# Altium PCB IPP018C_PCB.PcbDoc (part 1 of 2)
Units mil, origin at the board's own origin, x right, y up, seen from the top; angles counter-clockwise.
Board outline 3500 x 2700 mil, 4 copper layers (Top Layer, Mid-Layer 1, Mid-Layer 2, Bottom Layer), stack 90 mil thick; 62 components, 59 nets, 295 pads, 117 vias.
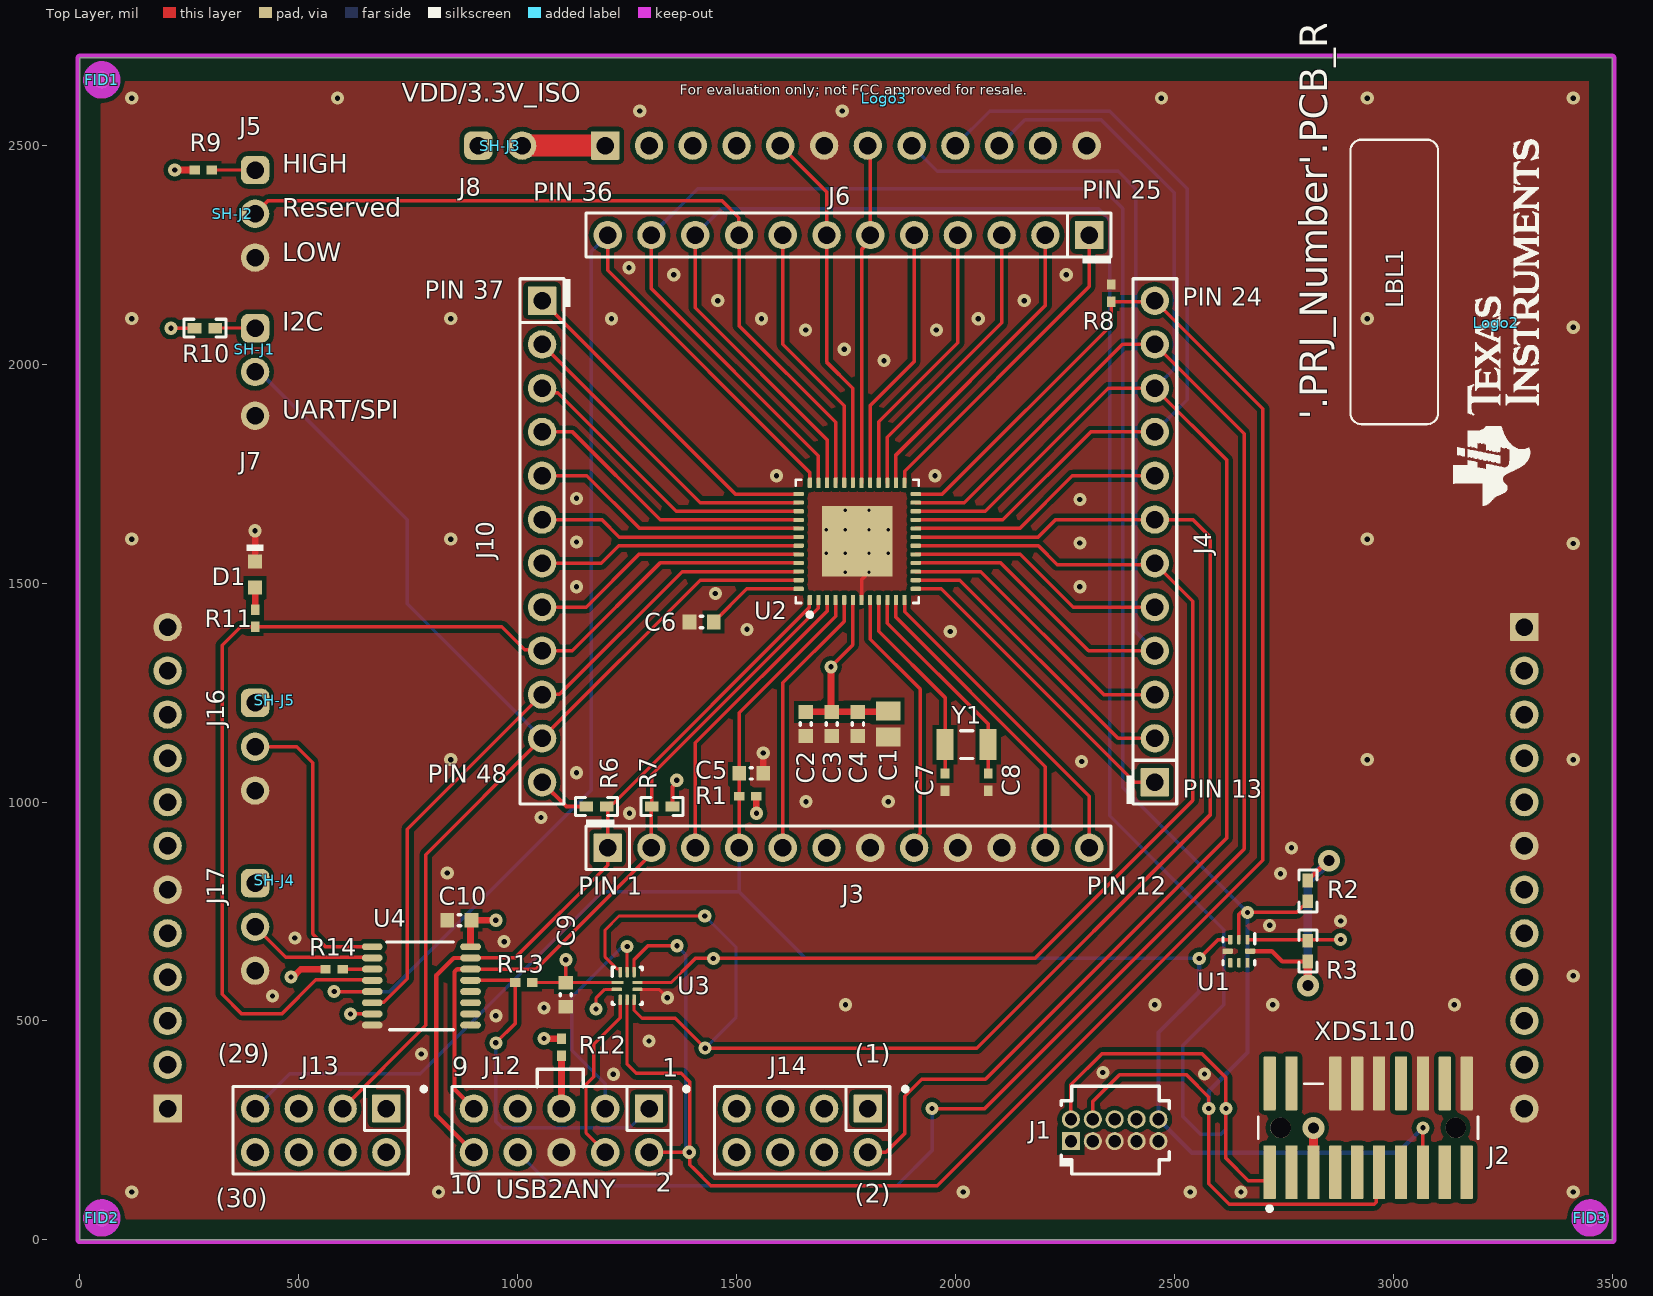
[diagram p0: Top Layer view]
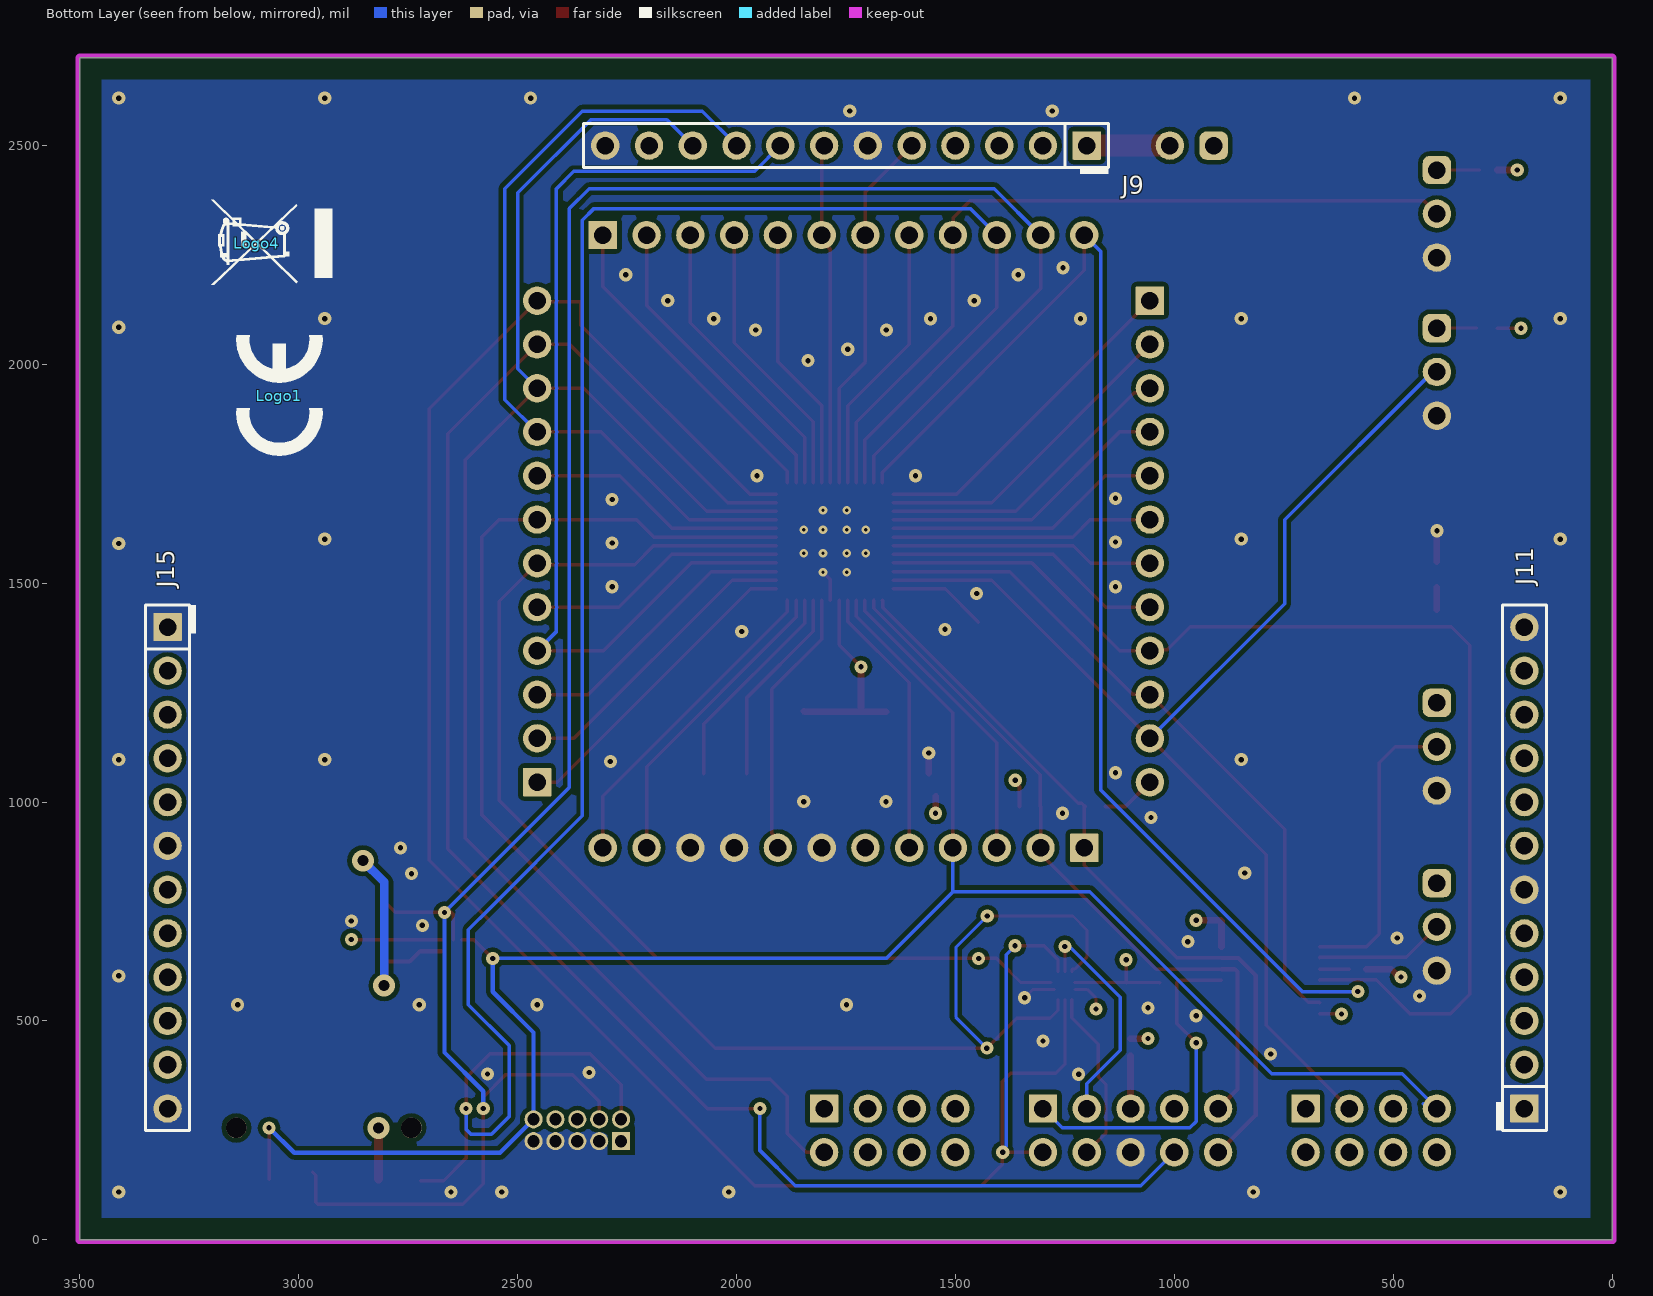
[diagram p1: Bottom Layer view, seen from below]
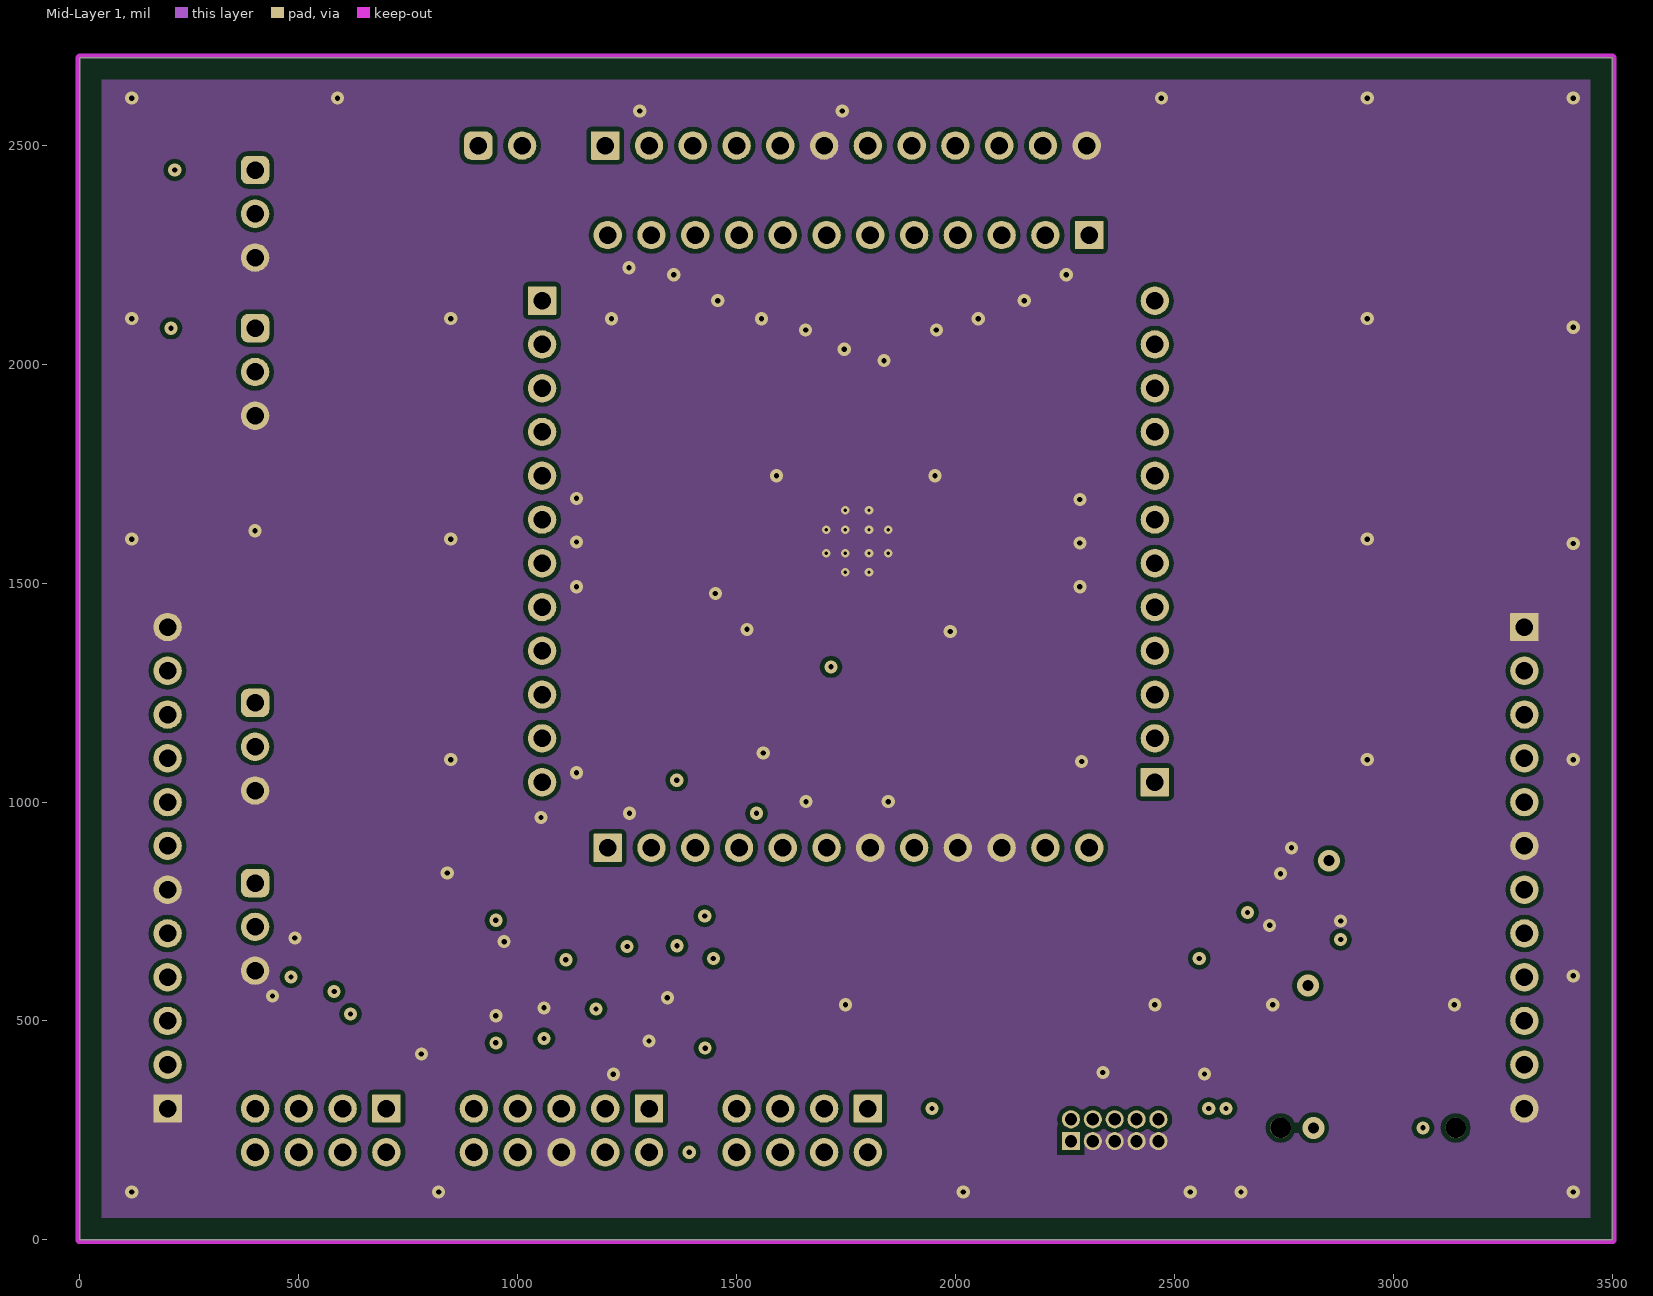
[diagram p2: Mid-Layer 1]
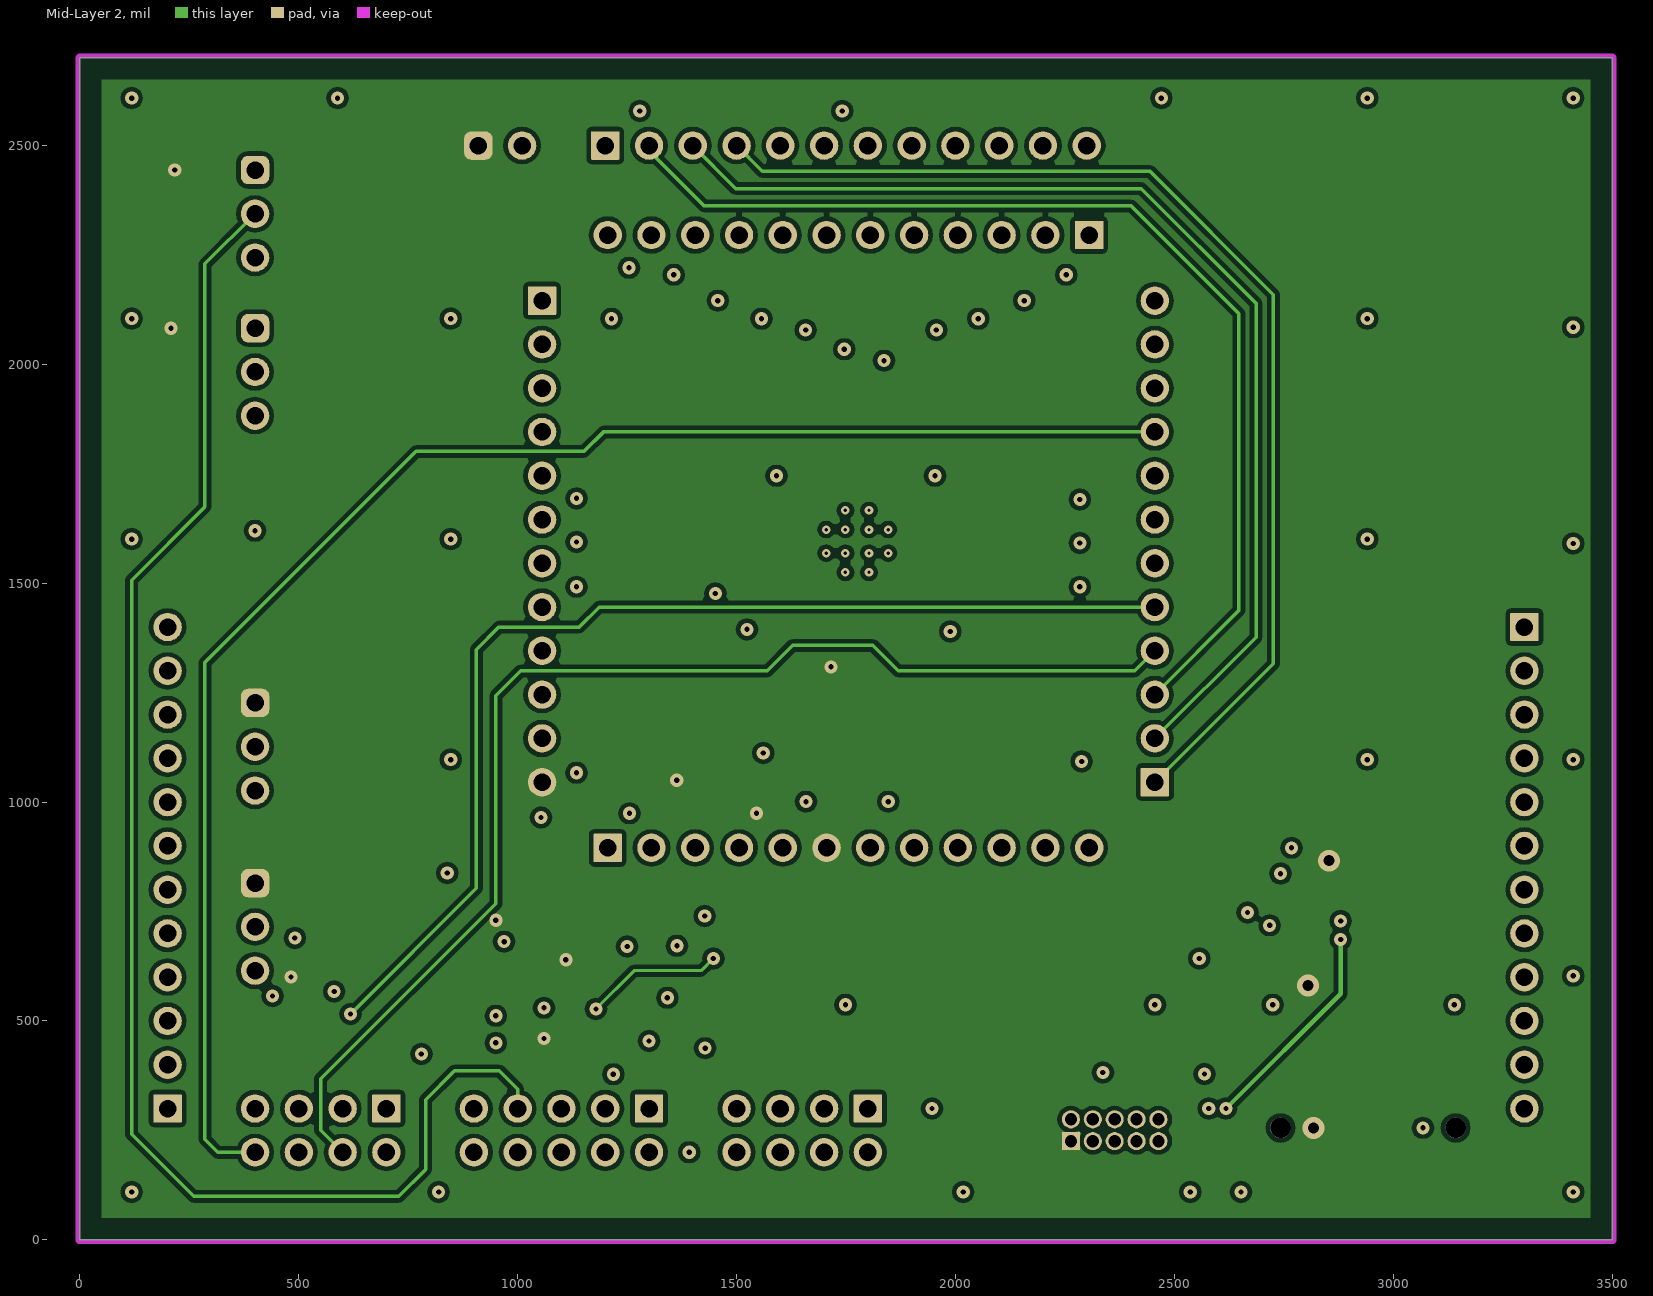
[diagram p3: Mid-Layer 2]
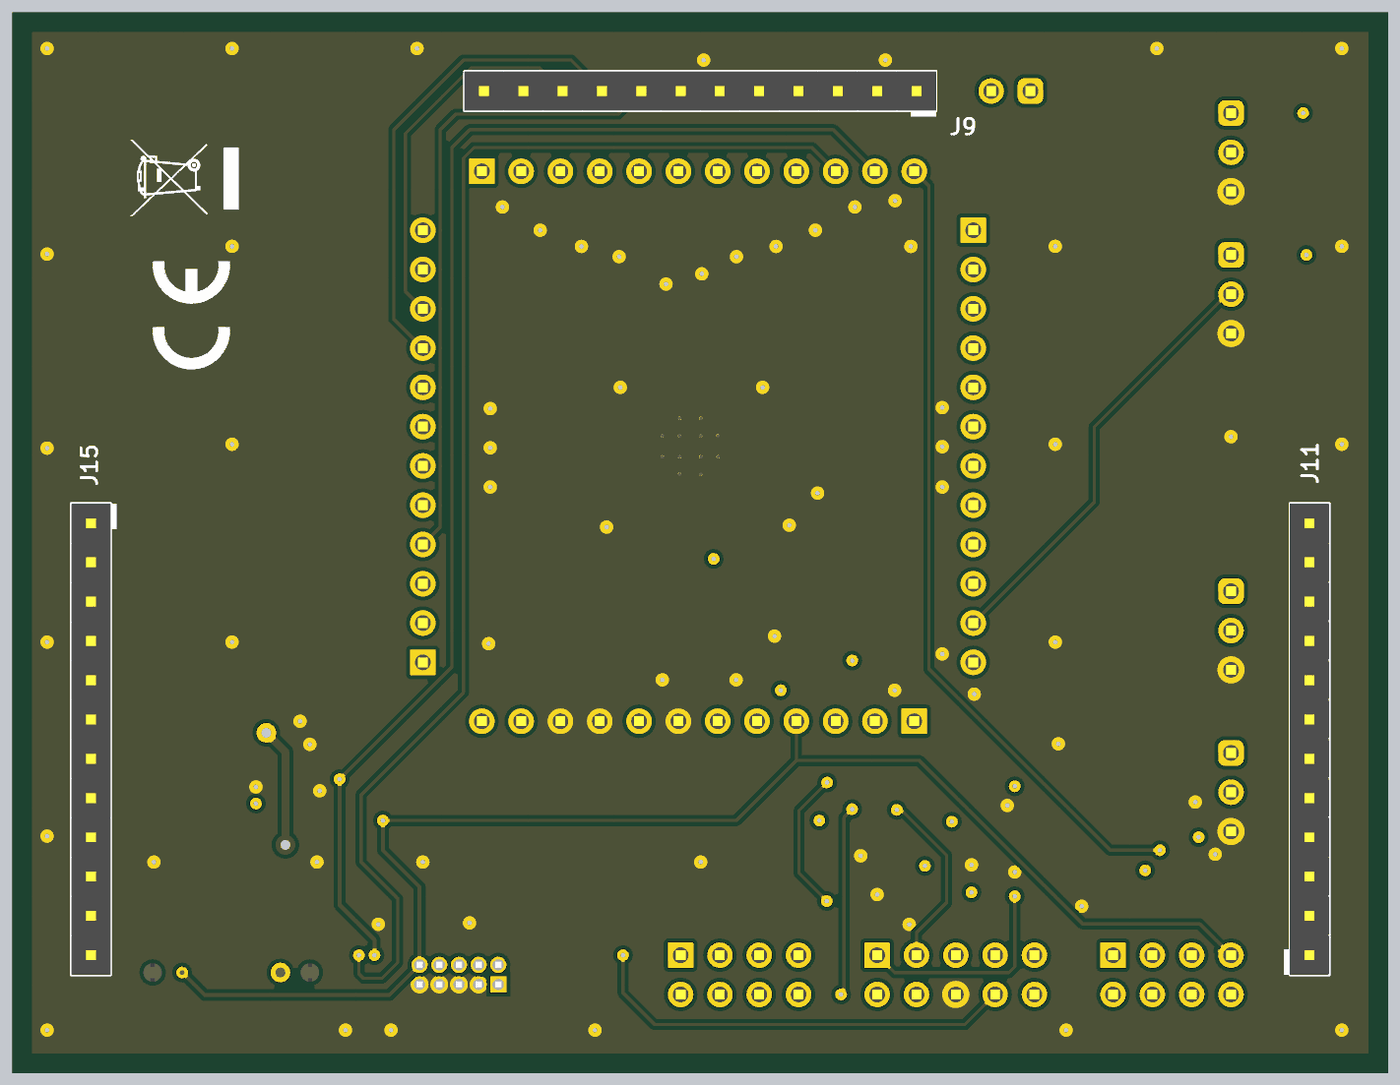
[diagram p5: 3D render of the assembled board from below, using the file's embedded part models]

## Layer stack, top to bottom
Top Solder: solder mask 0.4, Solder Resist, Dk 3.5
Top Layer: signal copper 1.4
Dielectric1: core 59.2, FR-4 High Tg, Dk 4.8
Mid-Layer 1: signal copper 1.4
Dielectric3: dielectric 12.6, FR-4, Dk 4.8
Mid-Layer 2: signal copper 1.4
Dielectric2: dielectric 12.6, FR-4, Dk 4.8
Bottom Layer: signal copper 1.4
Bottom Solder: solder mask 0.4, Solder Resist, Dk 3.5

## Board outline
0,0 3500,0 3500,2700 0,2700

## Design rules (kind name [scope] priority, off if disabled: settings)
AcuteAngle [All] p1: minimum=4.50000000000000E+0001 checktracksonly=FALSE
AssemblyTestPointUsage [All] p1: valid=2
BoardOutlineClearance BoardOutlineClearance_MountingHoles [OnCopper and InComponentClass('Mounting Holes')] p1: gap=39.37 ignorepadtopadclearanceinfootprint=FALSE
BoardOutlineClearance BoardOutlineClearance_Poly [OnCopper and IsPoly] p2: gap=25 ignorepadtopadclearanceinfootprint=FALSE
BoardOutlineClearance [OnCopper and Not InComponentClass('Logo') and not InComponentClass('FiducialMark') and not InRegion(1000,500,4000,800) and not InPoly] p3: gap=40 ignorepadtopadclearanceinfootprint=FALSE
Clearance Clearance_Keepouts [((IsTrack Or IsArc) And Not InPoly) And IsFree and IsKeepOut vs ((IsTrack Or IsArc) And Not InPoly) And IsFree and IsKeepOut] p1: gap=0 ignorepadtopadclearanceinfootprint=FALSE
Clearance Clearance_Poly [InPolygon] p2: gap=10 ignorepadtopadclearanceinfootprint=TRUE
Clearance Clearance_FiducialMark [IsKeepOut and InComponentClass('FiducialMark') vs IsPad and InComponentClass('FiducialMark')] p3: gap=0 ignorepadtopadclearanceinfootprint=FALSE
Clearance [All] p4: gap=7.87 ignorepadtopadclearanceinfootprint=TRUE
ComponentClearance ComponentClearance_MountingHoles_FiducialMarks [InComponentClass('Mounting Holes') vs InComponentClass('FiducialMark')] p1: gap=50 collisioncheckmode=3 verticalgap=10 showdistances=FALSE
ComponentClearance ComponentClearance_Shunt [InComponentClass('Header') vs InComponentClass('Shunt')] p2: gap=0 collisioncheckmode=3 verticalgap=0 showdistances=FALSE
ComponentClearance ComponentClearance_Logo [InComponentClass('Logo')] p3: gap=30 collisioncheckmode=3 verticalgap=10 showdistances=FALSE
ComponentClearance ComponentClearance_ScrewToNut [(HasFootprint('NY PMS 440 0025 PH')) vs (HasFootprint('Keystone_1902C'))] p4: gap=5 collisioncheckmode=3 verticalgap=10 showdistances=FALSE
ComponentClearance ComponentClearance_MountingHoles [InComponentClass('Mounting Holes')] p5: gap=100 collisioncheckmode=3 verticalgap=100000 showdistances=FALSE
ComponentClearance ComponentClearance_SmallPassives [HasFootprint('0201*') or HasFootprint('0402*') or HasFootprint('0508') or HasFootprint('0603*') or HasFootprint('0612') or HasFootprint('0805*') or HasFootprint('0815*') or HasFootprint('0830*') or HasFootprint('1206*') or HasFootprint('1210*') or HasFootprint('1808*') or HasFootprint('1812*') or HasFootprint('1825*') or HasFootprint('2010*') or HasFootprint('2220*') or HasFootprint('2225*') or HasFootprint('2512*') or HasFootprint('2728*') or HasFootprint('3518*') vs HasFootprint('0201*') or HasFootprint('0402*') or HasFootprint('0508') or HasFootprint('0603*') or HasFootprint('0612') or HasFootprint('0805*') or HasFootprint('0815*') or HasFootprint('0830*') or HasFootprint('1206*') or HasFootprint('1210*') or HasFootprint('1808*') or HasFootprint('1812*') or HasFootprint('1825*') or HasFootprint('2010*') or HasFootprint('2220*') or HasFootprint('2225*') or HasFootprint('2512*') or HasFootprint('2728*') or HasFootprint('3518*')] p6: gap=14.96 collisioncheckmode=3 verticalgap=10 showdistances=FALSE
ComponentClearance ComponentClearance_THtoSMT [IsThruComponent vs IsSMTComponent] p7: gap=30 collisioncheckmode=3 verticalgap=30 showdistances=FALSE
ComponentClearance ComponentClearance_THtoTH [IsThruComponent vs IsThruComponent] p8: gap=20 collisioncheckmode=3 verticalgap=30 showdistances=FALSE
ComponentClearance [All] p9: gap=20 collisioncheckmode=3 verticalgap=10 showdistances=FALSE
DiffPairsRouting [All] p1: maxlimit=100 minlimit=10 mostfreqgap=10 toplayer_minwidth=15 toplayer_maxwidth=15 toplayer_prefwidth=15 midlayer1_minwidth=15 midlayer1_maxwidth=15 midlayer1_prefwidth=15 midlayer2_minwidth=15 midlayer2_maxwidth=15 midlayer2_prefwidth=15 bottomlayer_minwidth=15 bottomlayer_maxwidth=15 bottomlayer_prefwidth=15 maxuncoupledlength=1000
FabricationTestPointUsage TestPointUsage [All] p1: valid=2 allowmultiple=FALSE
FabricationTestpoint Testpoint [All] p1: side=3 testpointundercomponent=TRUE minsize=40 maxsize=100 preferedsize=60 minholesize=0 maxholesize=40 preferedholesize=32 testpointgrid=1 allowsidetop=TRUE allowsidebottom=TRUE usegrid=TRUE gridtolerance=0.01
FanoutControl Fanout_LCC [IsLCC] p1: bgadir=Out bgaviamode=Centered fanoutstyle=Auto fanoutdirection=Alternating viagrid=1 // Fanout_LCC (Default Rule)
FanoutControl Fanout_BGA [IsBGA] p2: bgadir=Out bgaviamode=Centered fanoutstyle=Auto fanoutdirection=Alternating viagrid=1 // Fanout_BGA (Default Rule)
FanoutControl Fanout_Default [All] p4: bgadir=Out bgaviamode=Centered fanoutstyle=Auto fanoutdirection=Alternating viagrid=1 // Fanout_Default (Default Rule)
FanoutControl Fanout_Small [(CompPinCount < 5)] p5: bgadir=Out bgaviamode=Centered fanoutstyle=Auto fanoutdirection=OutThenIn viagrid=1 // Fanout_Small (Default Rule)
HoleSize [All] p1: absolutevalues=TRUE maxlimit=251 minlimit=7.87 maxpercent=80.000 minpercent=20.000
MinimumAnnularRing MinimumAnnularRing_ThermalPadVias [IsVia and InAnyComponent] p1: minimumring=5.91
MinimumAnnularRing [All] p2: minimumring=7.87
MinimumSolderMaskSliver MinimumSolderMaskSliver_Logo [InComponentClass('Logo') vs InComponentClass('Logo')] p1: minsoldermaskwidth=0.7
MinimumSolderMaskSliver [All] p2: minsoldermaskwidth=3.94
PlaneConnect [All] p1: planeconnectstyle=Direct reliefexpansion=10 reliefentries=4 reliefconductorwidth=10 reliefairgap=10
PolygonConnect [All] p1: connectstyle=Direct reliefconductorwidth=10 reliefentries=4 polygonreliefangle="90 Angle" airgapwidth=10
RoutingLayers [All] p1: top layer_v5=TRUE mid layer 1_v5=FALSE mid layer 2_v5=TRUE bottom layer_v5=TRUE
RoutingVias ThermalPadVias [IsVia and InAnyComponent] p1: holewidth=7.87 width=19.68 viastyle="Through Hole" minholewidth=7.87 minwidth=19.68 maxholewidth=12.99 maxwidth=23.62
RoutingVias [All] p2: holewidth=16 width=34 viastyle="Through Hole" minholewidth=7.87 minwidth=24 maxholewidth=40 maxwidth=65
SilkToBoardRegionClearance [Not ((IsComment or IsDesignator) And (Hide <> 'False')) and not InRegion(1000,500,4000,800)] p1:
SilkToSilkClearance SilkToSilkClearance_Pb-FreeLogo [(HasFootprint('Pb-Free_Overlay_Medium') OR HasFootprint('Pb-Free_Overlay_Small')) vs (HasFootprint('Pb-Free_Overlay_Medium') OR HasFootprint('Pb-Free_Overlay_Small'))] p1: silktosilkclearance=0
SilkToSilkClearance [All] p2: silktosilkclearance=3.94
SilkToSolderMaskClearance SilkToComponentPadClearance [(IsPad or IsFill or IsRegion) and InAnycomponent] p1: minsilkscreentomaskgap=5 clearancetoexposedcopper=TRUE
SilkToSolderMaskClearance "Silk to Solder Mask Opening" [All] p2: minsilkscreentomaskgap=3.94 clearancetoexposedcopper=FALSE
SolderMaskExpansion [All] p1: expansion=1.97 istentingtop=FALSE
SupplyNets "Schematic Supply Nets_1" [InNet('VDD')] p1: voltage=0.000
SupplyNets "Schematic Supply Nets" [InNet('GND_ISO')] p2: voltage=0.000
UnRoutedNet [All] p1: checkbadconnections=TRUE
Width [All] p1: maxlimit=50 minlimit=6 preferedwidth=10 midlayer1_maxwidth=20 midlayer2_maxwidth=20 minimp=50.000000 maximp=50.000000 favimp=50.000000 checkconnectedcopper=TRUE
13 further rules are at their usual default settings.

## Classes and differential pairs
component class Shunt: SH-J1 SH-J2 SH-J3 SH-J4 SH-J5
component class IPP018C: 7 C1 C2 C3 C4 C5 C6 C7 C8 C9 C10 D1 J1 J2 J3 J4 J5 J6 J7 J8 J9 J10 J11 J12 J13 J14 J15 J16 J17 R1 R2 R3 R6 R7 R8 R9 R10 R11 R12 R13 R14 SH-J1 SH-J2 SH-J3 SH-J4 SH-J5 U1 U2 U3 U4 Y1
component class Header: 7 J3 J4 J5 J6 J7 J8 J9 J10 J11 J12 J13 J14 J15 J16 J17
component class Logo: Logo2
component class IPP018C_Hardware: FID1 FID2 FID3 LBL1 Logo1 Logo2 Logo3 Logo4 ZZ1 ZZ2 ZZ3 ZZ4
component class FiducialMark: FID1 FID2 FID3
component class AssemblyNote: ZZ1 ZZ2 ZZ3 ZZ4
component class Label: LBL1

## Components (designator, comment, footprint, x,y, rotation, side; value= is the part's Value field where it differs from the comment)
C1 "885012207026" 0805L 1846.46,1178.53 r90 top value=10uF
C2 "885012206046" 0603L 1657.87,1178.53 r90 top value=0.1uF
C3 "885012206046" 0603L 1717.52,1178.53 r90 top value=0.1uF
C4 "885012206046" 0603L 1777.17,1178.53 r90 top value=0.1uF
C5 "885012206083" 0603L 1533.46,1065.59 r0 top value=1000pF
C6 "GCM188R71C474KA55D" 0603L 1420.16,1411.42 r0 top value=0.47uF
C7 "CL05C120JB5NNNC" 0402L 1976.18,1045.59 r270 top value=12pF
C8 "CL05C120JB5NNNC" 0402L 2074.8,1045.59 r270 top value=12pF
C9 "885012206046" 0603L 1110,560 r90 top value=0.1uF
C10 "885012206046" 0603L 866.61,730 r0 top value=0.1uF
D1 "LTST-C190KGKT" LED_LTST-C190_G 400,1520 r90 top value=Green
FID1 "Fiducial" Fiducial10-20 50,2650 r0 top
FID2 "Fiducial" Fiducial10-20 50,50 r0 top
FID3 "Fiducial" Fiducial10-20 3450,50 r0 top
J1 "FTSH-105-01-F-D-K" Samtec_FTSH-105-01-x-D-K 2363.8,250.42 r90 top
J2 "FTR-110-03-G-D-LC-06" FP-FTR-110-03-G-D-LC-06_HDR19-MFG 2942.91,255.91 r0 top
J3 "TSW-112-07-G-S" TSW-112-07-G-S 1755.59,895.59 r0 top locked
J4 "TSW-112-07-G-S" TSW-112-07-G-S 2455.59,1595.59 r90 top
J5 "TSW-103-07-G-S" TSW-103-07-G-S 400,2344.09 r270 top
J6 "TSW-112-07-G-S" TSW-112-07-G-S 1755.59,2295.59 r180 top
J7 "TSW-103-07-G-S" TSW-103-07-G-S 400,1982.7 r270 top
J8 "TSW-102-07-G-S" TSW-102-07-G-S 960,2500 r0 top
J9 "TSW-112-07-G-S" TSW-112-07-G-S 1750,2500 r0 bottom
J10 "TSW-112-07-G-S" TSW-112-07-G-S 1055.59,1595.59 r270 top
J11 "TSW-112-07-G-S" TSW-112-07-G-S 200,850 r90 bottom
J12 "TSW-105-07-G-D" TSW-105-07-G-D 1100,250 r180 top
J13 "TSW-104-07-G-D" TSW-104-07-G-D 550,250 r180 top
J14 "TSW-104-07-G-D" TSW-104-07-G-D 1650,250 r180 top
J15 "TSW-112-07-G-S" TSW-112-07-G-S 3300,850 r270 bottom
J16 "TSW-103-07-G-S" TSW-103-07-G-S 400,1126.51 r270 top
J17 "TSW-103-07-G-S" TSW-103-07-G-S 400,715 r270 top
LBL1 "THT-14-423-10" Label_650x200 3002.52,2188.34 r90 top
Logo1 "CE Mark" CE_Mark_5mm 3044.36,1928.93 r90 bottom
Logo2 "Texas Instruments" TI_Stacked_Overlay_Small 3235,2095.52 r90 top
Logo3 "FCC disclaimer" FCC_disclaimer 1837.11,2608.27 r0 top
Logo4 "WEEE logo" WEEE_Minimum 3096.14,2277.16 r90 bottom
R1 "CRCW040247K0JNED" 0402L 1525.59,1013.78 r0 top value=47k
R2 "CRCW04024K70JNED" 0402 2805.12,797.24 r270 top value=4.7k
R3 "CRCW04024K70JNED" 0402 2805.12,659.45 r90 top value=4.7k
R6 "CRCW04024K70JNED" 0402 1180,989.84 r180 top value=4.7k
R7 "CRCW04024K70JNED" 0402 1330,989.84 r0 top value=4.7k
R8 "CRCW04022M00FKED" 0402L 2355.59,2162.97 r90 top value=2.00Meg
R9 "CRCW040247K0JNED" 0402L 281.5,2444.09 r180 top value=47k
R10 "CRCW04024K70JNED" 0402 285.43,2082.7 r0 top value=4.7k
R11 "CRCW0402330RJNED" 0402L 400,1420 r270 top value=330
R12 "ERJ-2GE0R00X" 0402L 1100,440 r270 top value=0
R13 "CRCW040247K0JNED" 0402L 1013.78,587.87 r0 top value=47k
R14 "CRCW040247K0JNED" 0402L 580.71,618.39 r180 top value=47k
SH-J1 "SPC02SYAN" SPC02SYAN 399.63,2034.5 r90 top value=1x2
SH-J2 "SPC02SYAN" SPC02SYAN 348.65,2344.09 r180 top value=1x2
SH-J3 "SPC02SYAN" SPC02SYAN 960,2500 r180 top value=1x2
SH-J4 "SPC02SYAN" SPC02SYAN 445.21,821.42 r180 top value=1x2
SH-J5 "SPC02SYAN" SPC02SYAN 445.21,1232.91 r0 top value=1x2
U1 "TPD6E004RSER" RSE0008A 2647.64,659.45 r270 top
U2 "MSPM0G1107SRGZ" RGZ0048B-MFG 1775.59,1595.59 r90 top
U3 "TS3A5223RSWR" RSW0010A 1250,580 r0 top
U4 "PCA9538PWR" PW0016A_L 780,580 r0 top
Y1 "FC-135 32.7680KA-AG0" Epson_FC-135 2025.39,1131.18 r0 top
ZZ1 "This Assembly Note is for PCB labels only" AssemblyNoteLabel 155.47,5079.73 r0 top
ZZ2 "These assemblies are ESD sensitive, ESD precautions shall be observed." AssemblyNote 155.47,4970.85 r0 top
ZZ3 "These assemblies must be clean and free from flux and all contaminants. Use of no clean flux is not acceptable." AssemblyNote 155.47,4882.29 r0 top
ZZ4 "These assemblies must comply with workmanship standards IPC-A-610 Class 2, unless otherwise specified." AssemblyNote 155.47,4793.73 r0 top

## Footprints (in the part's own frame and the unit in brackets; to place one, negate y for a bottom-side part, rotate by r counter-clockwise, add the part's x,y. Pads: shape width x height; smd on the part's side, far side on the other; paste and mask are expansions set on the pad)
0402 [mm] "0402 from SM-752 data"
  rect 0.8x0.6 smd: 1(-0.6,0) 2(0.6,0)
  silkscreen extent -1.22,-0.52 1.22,0.52, body extent -0.55,-0.3 0.55,0.3, height 0.6
0402L [mm] "0402 from SM-752 data"
  rect 0.6x0.5 smd: 1(-0.5,0) 2(0.5,0)
  body extent -0.55,-0.3 0.55,0.3, height 0.6
0603L [mm] "0603 from SM-752 data"
  rect 0.8x0.85 smd: 1(-0.7,0) 2(0.7,0)
  silkscreen extent -0.07,-0.33 0.07,0.33, body extent -0.87,-0.47 0.87,0.47, height 1
0805L [mm] "0805 from SM-752 data"
  rect 1.1x1.4 smd: 1(-0.75,0) 2(0.75,0)
  body extent -1.1,-0.72 1.1,0.72, height 1.45
AssemblyNote [mil] "Assembly Note"
AssemblyNoteLabel [mil] "Assembly Note for PCB Labels"
CE_Mark_5mm [mil] "Minimum text height for CE Mark"
  silkscreen extent -138,-98 138,98
Epson_FC-135 [mm] "SMD, 2-Leads, Body 3.2x1.5mm"
  rect 1x1.8 smd: 1(-1.25,0) 2(1.25,0)
  silkscreen extent -0.35,-0.8 0.35,0.8, body extent -1.65,-0.8 1.65,0.8, height 0.9
FCC_disclaimer [mil]
Fiducial10-20 [mm]
  round 1 smd mask+0.5: 1(0,0)
  Top Layer keep-out circle w1.178: c0,0 r0.5
FP-FTR-110-03-G-D-LC-06_HDR19-MFG [mm]
  rrect14% 0.711x3.125 smd paste+0 mask+0: 1(-5.715,-2.578) 2(-5.715,2.578) 3(-4.445,-2.578) 4(-4.445,2.578) 5(-3.175,-2.578) 7(-1.905,-2.578) 8(-1.905,2.578) 9(-0.635,-2.578) 10(-0.635,2.578) 11(0.635,-2.578) 12(0.635,2.578) 13(1.905,-2.578) 14(1.905,2.578) 15(3.175,-2.578) 16(3.175,2.578) 17(4.445,-2.578) 18(4.445,2.578) 19(5.715,-2.578) 20(5.715,2.578)
  round 1.194 hole 1.194 unplated paste-2539.97 mask+0: ""(-5.08,0) ""(5.08,0)
  silkscreen extent -6.38,-4.81 6.38,2.56, body extent -6.48,-4.24 6.48,4.24, height 0.25
Label_650x200 [mil] "Thermal Transfer Label"
  round 1 on Mech13: 0(0,0)
  silkscreen extent -325,-100 325,100, body extent -325,-100 325,100, height 1
LED_LTST-C190_G [mm] "Lite-On"
  rect 0.8x0.8 smd: 1(-0.75,0) 2(0.75,0)
  silkscreen extent 1.37,-0.5 1.75,0.5, body extent -0.85,-0.45 0.85,0.45, height 0.9
PW0016A_L [mm] "TSOP, 16-Leads, Body 5x4.4mm, Pitch 0.65mm, IPC High Density"
  oval 1.2x0.4 smd: 1(-2.85,2.275) 2(-2.85,1.625) 3(-2.85,0.975) 4(-2.85,0.325) 5(-2.85,-0.325) 6(-2.85,-0.975) 7(-2.85,-1.625) 8(-2.85,-2.275) 9(2.85,-2.275) 10(2.85,-1.625) 11(2.85,-0.975) 12(2.85,-0.325) 13(2.85,0.325) 14(2.85,0.975) 15(2.85,1.625) 16(2.85,2.275)
  silkscreen extent -2,-2.55 1.85,2.55, body extent -3.21,-2.5 3.21,2.5, height 1
RGZ0048B-MFG [mm]
  rrect42% 0.6x0.24 smd paste+0 mask+0: 1(-3.4,2.75) 2(-3.4,2.25) 3(-3.4,1.75) 4(-3.4,1.25) 5(-3.4,0.75) 6(-3.4,0.25) 7(-3.4,-0.25) 8(-3.4,-0.75) 9(-3.4,-1.25) 10(-3.4,-1.75) 11(-3.4,-2.25) 12(-3.4,-2.75) 25(3.4,-2.75) 26(3.4,-2.25) 27(3.4,-1.75) 28(3.4,-1.25) 29(3.4,-0.75) 30(3.4,-0.25) 31(3.4,0.25) 32(3.4,0.75) 33(3.4,1.25) 34(3.4,1.75) 35(3.4,2.25) 36(3.4,2.75)
  rrect42% 0.24x0.6 smd paste+0 mask+0: 13(-2.75,-3.4) 14(-2.25,-3.4) 15(-1.75,-3.4) 16(-1.25,-3.4) 17(-0.75,-3.4) 18(-0.25,-3.4) 19(0.25,-3.4) 20(0.75,-3.4) 21(1.25,-3.4) 22(1.75,-3.4) 23(2.25,-3.4) 24(2.75,-3.4) 37(2.75,3.4) 38(2.25,3.4) 39(1.75,3.4) 40(1.25,3.4) 41(0.75,3.4) 42(0.25,3.4) 43(-0.25,3.4) 44(-0.75,3.4) 45(-1.25,3.4) 46(-1.75,3.4) 47(-2.25,3.4) 48(-2.75,3.4)
  rrect2% 4.1x4.1 smd paste-1000 mask+0: 49(0,0)
  silkscreen extent -4.37,-3.57 3.57,3.57, body extent -3.8,-3.8 3.8,3.8, height 0.25
RSE0008A [mm] "QFN, 8-Leads, Body 1.5x1.5mm, Pitch 0.5mm, TI Recommended"
  rrect40% 0.55x0.25 smd: 1(-0.675,0.5) 3(-0.675,-0.5) 5(0.675,-0.5) 7(0.675,0.5)
  rrect50% 0.55x0.2 smd: 2(-0.675,0) 6(0.675,0)
  rrect33% 0.3x0.6 smd: 4(0,-0.65) 8(0,0.65)
  silkscreen extent -1.02,-0.92 0.77,0.93, body extent -0.75,-0.75 0.75,0.75, height 0.6
RSW0010A [mm] "QFN, 10-Leads, Body 1.8x1.4 mm, Pitch 0.4mm, TI Recommended"
  rrect50% 0.7x0.2 smd: 1(-0.55,0.2)
  rrect50% 0.6x0.2 smd: 2(-0.6,-0.2) 6(0.6,-0.2) 7(0.6,0.2)
  rrect50% 0.2x0.6 smd: 3(-0.4,-0.8) 4(0,-0.8) 5(0.4,-0.8) 8(0.4,0.8) 9(0,0.8) 10(-0.4,0.8)
  silkscreen extent -0.88,-1.08 0.88,1.08, body extent -0.7,-0.9 0.7,0.9, height 0.56
Samtec_FTSH-105-01-x-D-K [mm] "Header, 1.27 mm, 5x2, TH"
  rect 1.05x1.05 hole 0.71: 1(-0.635,2.54)
  round 1.05 hole 0.71: 2(0.635,2.54) 3(-0.635,1.27) 4(0.635,1.27) 5(-0.635,0) 6(0.635,0) 7(-0.635,-1.27) 8(0.635,-1.27) 9(-0.635,-2.54) 10(0.635,-2.54)
  silkscreen extent -2.54,-3.17 2.54,3.2, body extent -2.54,-3.17 2.54,3.1, height 5.73
SPC02SYAN [mil] "SULLINS"
  round 1 on Mech3: 0(0,0)
  body extent -98,-47 99,47, height 366
TI_Stacked_Overlay_Small [mil]
  silkscreen extent -418,-98 418,98
TSW-102-07-G-S [mm] "Samtec 100mil, 1x2, 230 mil above insulator"
  rrect50% 1.65x1.65 hole 1.016: 1(-1.27,0)
  round 1.65 hole 1.016: 2(1.27,0)
  body extent -2.54,-1.27 2.54,1.27, height 8.38
TSW-103-07-G-S [mm] "Samtec 100mil, 1x3, 230 mil above insulator"
  rrect50% 1.65x1.65 hole 1.016: 1(-2.54,0)
  round 1.65 hole 1.016: 2(0,0) 3(2.54,0)
  body extent -3.81,-1.27 3.81,1.27, height 8.38
TSW-104-07-G-D [mm] "Samtec 100mil, 2x4, 230 mil above insulator"
  rrect6% 1.65x1.65 hole 1.016: 1(-3.81,-1.27)
  round 1.65 hole 1.016: 2(-3.81,1.27) 3(-1.27,-1.27) 4(-1.27,1.27) 5(1.27,-1.27) 6(1.27,1.27) 7(3.81,-1.27) 8(3.81,1.27)
  silkscreen extent -6.11,-2.54 5.08,2.54, body extent -5.08,-2.54 5.08,2.54, height 8.38
TSW-105-07-G-D [mm] "Samtec 100mil, 2x5, 230 mil above insulator"
  rrect6% 1.65x1.65 hole 1.016: 1(-5.08,-1.27)
  round 1.65 hole 1.016: 2(-5.08,1.27) 3(-2.54,-1.27) 4(-2.54,1.27) 5(0,-1.27) 6(0,1.27) 7(2.54,-1.27) 8(2.54,1.27) 9(5.08,-1.27) 10(5.08,1.27)
  silkscreen extent -7.38,-2.54 6.35,2.54, body extent -6.35,-2.54 6.35,2.54, height 8.38
TSW-112-07-G-S [mm] "Samtec 100mil, 1x12, 230 mil above insulator"
  rrect6% 1.65x1.65 hole 1.016 mask+0: 1(-13.97,0)
  round 1.65 hole 1.016 mask+0: 2(-11.43,0) 3(-8.89,0) 4(-6.35,0) 5(-3.81,0) 6(-1.27,0) 7(1.27,0) 8(3.81,0) 9(6.35,0) 10(8.89,0) 11(11.43,0) 12(13.97,0)
  silkscreen extent -15.24,-1.27 15.24,1.65, body extent -15.24,-1.27 15.24,1.27, height 8.38
WEEE_Minimum [mil] "WEEElie bin"
  silkscreen extent -95,-172 99,104

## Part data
C1: library part CMP-0007691-2, "CAP, CERM, 10 uF, 10 V, +/- 10%, X7R, 0805", Cap_Case=0805, Manufacturer="Wurth Elektronik", Supplier Part Number 1=710-885012207026, TempCo=X7R, Tolerance_%=10%, Value1=Unknown, Value2=10V, ValueDisplayed=10uF
C2 C3 C4 C9 C10: library part CMP-0006829-4, "CAP, CERM, 0.1 uF, 16 V, +/- 10%, X7R, 0603", Cap_Case=0603, Manufacturer="Wurth Elektronik", Supplier Part Number 1=710-885012206046, TempCo=X7R, Tolerance_%=10%, Value1=Unknown, Value2=16V, ValueDisplayed=0.1uF
C5: library part CMP-0064933-4, "CAP, CERM, 1000 pF, 50 V,+/- 10%, X7R, 0603", Cap_Case=0603, Manufacturer="Wurth Elektronik", Supplier Part Number 1=732-8001-1-ND, TempCo=X7R, Tolerance_%=10%, Value1=Unknown, Value2=50V, ValueDisplayed=1000pF
C6: library part CMP-0007138-4, "CAP, CERM, 0.47 uF, 16 V, +/- 10%, X7R, AEC-Q200 Grade 1, 0603", Cap_Case=0603, Manufacturer=MuRata, Supplier Part Number 1=490-4775-1-ND, TempCo=X7R, Tolerance_%=10%, Value1=Unknown, Value2=16V, ValueDisplayed=0.47uF
C7 C8: library part CMP-0006345-2, "CAP, CERM, 12 pF, 50 V, +/- 5%, C0G/NP0, 0402", Cap_Case=0402, Manufacturer="Samsung Electro-Mechanics", Supplier Part Number 1=1276-1178-1-ND, TempCo=C0G/NP0, Tolerance_%=5%, Value1=Unknown, Value2=50V, ValueDisplayed=12pF
D1: library part CMP-0002840-2, "LED, Green, SMD", Color=green, Manufacturer=Lite-On, Value1=W, Value2=2V
FID1 FID2 FID3: library part CMP-0077181-1, "Fiducial mark.  There is nothing to buy or mount.", Manufacturer=N/A
J1: library part CMP-0075533-2, "Header, 1.27 mm, 5x2, Gold, TH", Color=Black, Manufacturer=Samtec, Supplier Part Number 1=FTSH-105-01-F-D-K-ND
J2: library part CMP-0092655-1, Current_A=3.1A, Digikey Part Number=SAM8791-ND, Manufacturer=Samtec, Mouser Part Number=200-FTR11003GDLC06, Operating Temperature Range="-55°C to +125°C"
J3 J4 J6 J9 J10 J11 J15: library part CMP-0075424-1, "Header, 100mil, 12x1, Gold, TH", Color=Black, Current_A=6.3A, Manufacturer=Samtec, Supplier Part Number 1=SAM1029-12-ND, Voltage_V=550V
J5 J7 J16 J17: library part CMP-0075407-2, "Header, 100mil, 3x1, Gold, TH", Color=Black, Current_A=6.3A, Manufacturer=Samtec, Supplier Part Number 1=SAM1029-03-ND, Voltage_V=550V
J8: library part CMP-0075405-2, "Header, 100mil, 2x1, Gold, TH", Color=Black, Current_A=6.3A, Manufacturer=Samtec, Supplier Part Number 1=SAM1029-02-ND, Voltage_V=550V
J12: library part CMP-0075410-2, "Header, 100mil, 5x2, Gold, TH", Color=Black, Current_A=6.3A, Manufacturer=Samtec, Supplier Part Number 1=SAM1028-05-ND, Voltage_V=550V
J13 J14: library part CMP-0075408-2, "Header, 100mil, 4x2, Gold, TH", Color=Black, Current_A=6.3A, Manufacturer=Samtec, Supplier Part Number 1=SAM1028-04-ND, Voltage_V=550V
LBL1: library part CMP-0003625-1, "Thermal Transfer Printable Labels, 0.650\" W x 0.200\" H - 10,000 per roll", Manufacturer=Brady, Supplier Part Number 1=97C5133
Logo1: library part CMP-0074844-1
Logo2: library part CMP-0074838-1, "Texas Instrument Corporate Signature"
Logo3: library part CMP-0074847-1, "FCC_disclaimer"
Logo4: library part CMP-0074769-1
R1 R9 R13 R14: library part CMP-0026935-3, "RES, 47 k, 5%, 0.063 W, AEC-Q200 Grade 0, 0402", Manufacturer=Vishay-Dale, Power_W=63mW, Supplier Part Number 1=541-47KJCT-ND, TempCo="200 ppm/C", Tolerance_%=5%, Value2=0.063W, Value_Code=47k0, ValueDisplayed=47k
R2 R3 R6 R7 R10: library part CMP-0026938-5, "RES, 4.7 k, 5%, 0.063 W, AEC-Q200 Grade 0, 0402", Manufacturer=Vishay-Dale, Power_W=63mW, Supplier Part Number 1=541-4.7KJCT-ND, TempCo="200 ppm/C", Tolerance_%=5%, Value2=0.063W, Value_Code=4k70, ValueDisplayed=4.7k
R8: library part CMP-0026245-2, "RES, 2.00 M, 1%, 0.063 W, AEC-Q200 Grade 0, 0402", Manufacturer=Vishay-Dale, Power_W=63mW, Supplier Part Number 1=541-2.00MLCT-ND, TempCo="100 ppm/C", Tolerance_%=1%, Value2=0.063W, Value_Code=2M00, ValueDisplayed=2.00M
R11: library part CMP-0026906-3, "RES, 330, 5%, 0.063 W, AEC-Q200 Grade 0, 0402", Manufacturer=Vishay-Dale, Power_W=63mW, Supplier Part Number 1=541-330JCT-ND, TempCo="200 ppm/C", Tolerance_%=5%, Value2=0.063W, Value_Code=330R, ValueDisplayed=330
R12: library part CMP-0026992-3, "RES, 0, 5%, 0.1 W, AEC-Q200 Grade 0, 0402", Manufacturer=Panasonic, Power_W=100mW, Supplier Part Number 1=P0.0JCT-ND, TempCo="600 ppm/C", Tolerance_%=5%, Value2=0.1W, Value_Code=0000, ValueDisplayed=0
SH-J1 SH-J2 SH-J3 SH-J4 SH-J5: library part CMP-0003642-1, "Shunt, 100mil, Flash Gold, Black", Manufacturer="Sullins Connector Solutions", Supplier Part Number 1=S9001-ND
U1: library part CMP-0043125-4, "Low-Capacitance 6-Channel +/-15 kV ESD Protection Array for High-Speed Data Interfaces, RSE0008A (UQFN-8)", Breakdown Voltage(Min)(V)=6, IO Capacitance(Typ)(pF)=1.6, IO Leakage Current(nA)=1, Manufacturer="Texas Instruments"
U2: library part CMP-0097891-1, "Mixed-Signal Microcontrollers", Frequency_Fixed=80MHz, Manufacturer="Texas Instruments", Max Supply Voltage=3.6V, Min Supply Voltage=1.62V, Operating Temperature Range="-40°C to +125°C"
U3: library part CMP-0085520-1, "0.5Ω Dual SPDT Bidirectional Analog Switch, RSW0010A (UQFN-10)", Alternate Manufacturer="Texas Instruments", Operating Temperature Range="-40 to 85 C", Rating=Catalog
U4: library part CMP-0043202-2, "Remote 8-Bit I2C and SMBus Low-Power I/O Expander With Interrupt Output, Reset, and Config Registers, PW0016A (TSSOP-16)", 5V Tolerant I/O=Yes, Manufacturer="Texas Instruments", Max Frequency(kHz)=400, Operating Temperature Range="-40 to 85 C", Rating=Catalog
Y1: library part CMP-0079303-1, "Crystal, 32.768 KHz, 20 ppm, 7 pF, SMD", Frequency_Fixed=32.768kHz, Frequency Stability="20 ppm", Load Capacitance="7 pF", Manufacturer=Epson, Supplier Part Number 1=732-FC135-32.76KAAG0
ZZ1: library part CMP-0003616-3
ZZ2: library part CMP-0077236-1
ZZ3: library part CMP-0077237-1
ZZ4: library part CMP-0077238-1

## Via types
v1: diameter 30, hole 12, Top Layer to Bottom Layer, 102 vias
v2: diameter 19.68, hole 7.87, Top Layer to Bottom Layer, tented both sides, 12 vias
v3: diameter 50, hole 25, Top Layer to Bottom Layer, 2 vias
v4: diameter 50, hole 25, Top Layer to Bottom Layer, tented both sides, 1 vias

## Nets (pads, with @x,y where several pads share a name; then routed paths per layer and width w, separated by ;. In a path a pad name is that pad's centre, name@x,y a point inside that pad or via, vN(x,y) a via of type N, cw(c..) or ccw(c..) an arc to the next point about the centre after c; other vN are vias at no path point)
3.3V_ISO: J8.2 J9.1 | length 190
  Top Layer w50: J8.2@1010,2500 J9.1@1200,2500
GND_ISO: C1.1 C2.1 C3.1 C4.1 C5.2 C6.1 C7.2 C8.2 C9.1 C10.1 D1.2 J1.3 J1.5 J1.7 J1.9 J2.8 J2.10 J2.12 J2.16 J2.20 J3.7 J3.9 J3.10 J5.3 J7.3 J9.6 J9.12 J11.1 J11.6 J11.12 J12.6 J15.1 J15.6 J15.12 J16.3 J17.3 R8.2 U1.4 U2.7 U2.49 U3.6 U4.8 | length 263.3
  Top Layer w7: U3.6@1273.62,572.13 1322.59,572.13 v1(1341.79,552.93)
  Top Layer w8: U2.7@1785.43,1461.73 1785.43,1507.6 v2(1802.56,1524.72)
  Top Layer w15: D1.2@400,1549.53 v1(400,1620) ; C5.2@1561.02,1065.59 v1(1561.02,1112.2)
  other v1: 118.11,109.25 819.37,109.25 2017.72,109.25 2536.57,109.25 2652.32,109.25 3411.32,109.25 1218.47,378.24 2568.9,378.58 2336.8,382.12 779.91,424.51 1300,454.42 950,511.81 1060,530 1748.8,537.11 2455.59,537.11 2724.8,537.11 3139.76,537.11 440.07,556.93 3411.32,603.15 969.01,681.18 490.83,689.82 2717.91,718.5 2880.12,728.35 2742.91,836.61 839.05,838.09 2767.91,895.59 1053.12,964.65 1255.59,974.41 1658.61,1001.02 1846.46,1001.02 1134.49,1067.01 2288.38,1093.05 846.9,1097.04 2940.86,1097.04 3411.32,1097.04 1988.19,1389.91 1523.62,1394.64 1451.52,1476.38 1134.49,1491.87 2284.17,1491.87 3411.32,1590.94 2284.17,1591.73 1134.49,1594.51 118.11,1600.79 846.9,1600.79 2940.86,1600.79 2284.17,1691.59 1134.49,1693.97 1591.32,1745.59 1953.34,1745.59 1837.07,2008.48 1746.06,2034.5 1657.87,2078.34 1956.34,2078.34 3411.32,2084.84 1214.26,2104.36 1557.15,2104.36 2052.26,2104.36 118.11,2104.53 846.9,2104.53 2940.86,2104.53 1457.15,2145.59 2157.15,2145.59 1356.61,2204.72 2253.11,2204.72 1254.41,2220.73 1278.95,2578.74 1741.39,2578.74 118.11,2608.27 588.57,2608.27 2470.4,2608.27 2940.86,2608.27 3411.32,2608.27
  other v2: 1748.62,1524.72 1704.72,1568.62 1748.62,1568.62 1802.56,1568.62 1846.46,1568.62 1704.72,1622.56 1748.62,1622.56 1802.56,1622.56 1846.46,1622.56 1748.62,1666.46 1802.56,1666.46
NetC6_2: C6.2 U2.48 | length 225.5
  Top Layer w8: C6.2@1447.72,1411.42 1523.62,1487.32 U2.48@1641.73,1487.32
NetC7_1: C7.1 U2.9 Y1.1 | length 459.2
  Top Layer w8: U2.9@1824.8,1461.73 1824.8,1390.35 1976.18,1238.98 Y1.1@1976.18,1131.18 C7.1@1976.18,1065.28
NetC8_1: C8.1 U2.10 Y1.2 | length 491.9
  Top Layer w8: U2.10@1844.49,1461.73 1844.49,1408.65 2074.61,1178.53 Y1.2@2074.61,1131.18 2074.61,1065.47 C8.1@2074.8,1065.28
NetD1_1: D1.1 R11.1 | length 50.8
  Top Layer w15: R11.1@400,1439.69 D1.1@400,1490.47
NetJ5_1: J5.1 R9.1 | length 98.8
  Top Layer w7: R9.1@301.18,2444.09 J5.1@400,2444.09
NetJ7_1: J7.1 R10.2 | length 90.9
  Top Layer w7: R10.2@309.06,2082.7 J7.1@400,2082.7
NetJ12_1: J12.1 R13.1 U4.13 | length 814.1
  Top Layer w8: U4.13@892.2,592.8 989.17,592.8 R13.1@994.09,587.87 994.09,494.09 v1(950,450)
  Bottom Layer w8: v1(950,450) 950,270.47 964.83,255.65 1255.65,255.65 J12.1@1300,300
NetJ12_3: J12.3 U3.9 | length 518.9
  Top Layer w7: U3.9@1250,611.5 v1(1250,670)
  Bottom Layer w8: J12.3@1200,300 1200,356.78 1123.46,433.32 1123.46,554.18 1235.07,665.79 1245.79,665.79 v1(1250,670)
NetJ12_4: J12.4 U3.3 | length 398.8
  Top Layer w7: J12.4@1200,200 1156.38,243.62 1156.38,295.49 cw(c1200,300) 1156.38,304.51 1156.38,355.23 1173.69,372.54 1173.69,446.75 1234.25,507.32 1234.25,530 U3.3@1234.25,548.5
NetJ12_5: J12.5 R12.2 | length 120.3
  Top Layer w15: J12.5@1100,300 R12.2@1100,420.31
NetJ16_2: J16.2 U4.1 | length 686.3
  Top Layer w8: J16.2@400,1126.51 495.14,1126.51 531.5,1090.16 531.5,698.82 560.75,669.57 U4.1@667.8,669.57
NetJ17_2: J17.2 U4.2 | length 298
  Top Layer w8: J17.2@400,715 469.74,645.26 667.8,645.26 U4.2@667.8,643.98
NetR14_1: R14.1 U4.3 | length 67.4
  Top Layer w8: R14.1@600.39,618.39 U4.3@667.8,618.39
"PA0_I2C0 SDA": J3.1 J12.10 R6.1 U2.1 U4.15 | length 1736.4
  Top Layer w8: U4.15@892.2,643.98 993.47,643.98 1205.29,855.8 1205.29,895.29 J3.1@1205.59,895.59 R6.1@1205.59,987.87 ; R6.1@1203.62,989.84 1211.43,997.65 1219.44,997.65 1666.6,1444.81 1666.6,1461.01 U2.1@1667.32,1461.73
  Top Layer w10: U4.15@892.2,643.98 853.95,643.98 814.27,604.3 814.27,284.73 899,200 J12.10@900,200
"PA1_I2C0 SCL": J3.2 J12.9 R7.1 U2.2 U4.14 | length 1629.9
  Top Layer w8: U4.14@892.2,618.39 1041.68,618.39 1305.59,882.3 1305.59,989.06 R7.1@1306.38,989.84 1306.38,1062.14 1686.85,1442.61 1686.85,1461.57 U2.2@1687.01,1461.73
  Top Layer w10: U4.14@892.2,618.39 861.57,618.39 855.71,612.53 855.71,344.29 J12.9@900,300
PA2/ROSC: J3.8 U2.8 | length 619.1
  Top Layer w8: U2.8@1805.12,1461.73 1805.12,1372.49 1919.29,1258.31 1919.29,928.76 1916.49,925.96 1916.49,906.49 J3.8@1905.59,895.59
"PA5 HFXIN": J3.11 U2.11 | length 707.6
  Top Layer w8: U2.11@1864.17,1461.73 1864.17,1422.09 2205.59,1080.67 J3.11@2205.59,895.59
"PA6 HFXOUT": J3.12 U2.12 | length 740.8
  Top Layer w8: U2.12@1883.86,1461.73 1883.97,1461.62 1883.97,1435.32 2305.59,1013.7 J3.12@2305.59,895.59
"PA7 INT": J4.1 J9.4 U2.13 | length 3322.5
  Top Layer w8: U2.13@1909.45,1487.32 1967.99,1487.32 2409.72,1045.59 J4.1@2455.59,1045.59
  Mid-Layer 2 w8: J9.4@1500,2500 1558.8,2441.2 2444.56,2441.2 2726.38,2159.38 2726.38,1316.38 J4.1@2455.59,1045.59
"PA8 OC ALERT": J4.4 J9.8 J13.4 U2.16 | length 5081.6
  Top Layer w8: U2.16@1909.45,1546.38 2103.35,1546.38 2304.13,1345.59 J4.4@2455.59,1345.59
  Mid-Layer 2 w8: J13.4@600,200 550,250 550,368.01 950,768.01 950,1242.91 1007.09,1300 1570.36,1300 1628.63,1358.27 1811.02,1358.27 1869.29,1300 2410,1300 J4.4@2455.59,1345.59
  Bottom Layer w8: J9.8@1900,2500 1958.8,2441.2 2371.8,2441.2 2411.42,2401.57 2411.42,2149.59 ccw(c2455.59,2145.59) 2411.42,2141.59 2411.42,2049.59 ccw(c2455.59,2045.59) 2411.42,2041.59 2411.42,1949.59 ccw(c2455.59,1945.59) 2411.42,1941.59 2411.42,1849.59 ccw(c2455.59,1845.59) 2411.42,1841.59 2411.42,1749.59 ccw(c2455.59,1745.59) 2411.42,1741.59 2411.42,1649.59 ccw(c2455.59,1645.59) 2411.42,1641.59 2411.42,1549.59 ccw(c2455.59,1545.59) 2411.42,1541.59 2411.42,1449.59 ccw(c2455.59,1445.59) 2411.42,1441.59 2411.42,1389.76 2413.76,1387.42 J4.4@2455.59,1345.59
"PA9 DIS PORTS": J4.5 U2.17 U4.7 | length 3187.3
  Top Layer w8: v1(618.24,516.02) U4.7@667.8,516.02 ; U2.17@1909.45,1566.06 2148.39,1566.06 2268.86,1445.59 J4.5@2455.59,1445.59
  Mid-Layer 2 w8: v1(618.24,516.02) 905.51,803.3 905.51,1348.43 957.09,1400 1140.5,1400 1186.09,1445.59 J4.5@2455.59,1445.59
"PA10 UART0_TX": J4.6 U2.18 U3.2 U3.7 | length 2973.1
  Top Layer w7: v1(1178.58,527.39) 1178.58,551.66 1199.04,572.13 U3.2@1226.38,572.13 ; U3.7@1281.43,587.87 1351,587.87 1376.34,613.21
  Top Layer w8: 1376.34,613.21 1405.97,642.85 v1(1446.98,642.85) 2181.52,642.85 2542.39,1003.71 2542.39,1458.8 J4.6@2455.59,1545.59 2452.55,1542.55 2232.93,1542.55 2189.73,1585.75 U2.18@1909.45,1585.75
  Mid-Layer 2 w7: v1(1178.58,527.39) 1266.19,615 1419.13,615 v1(1446.98,642.85)
"PA11 UART0_RX": J4.7 U2.19 U3.5 U3.10 | length 3653.2
  Top Layer w7: U3.10@1233.81,611.93 1233.81,619.22 1226.53,619.22 1199.87,645.88 1199.87,708.03 1231.59,739.75 v1(1427.17,739.75) ; U3.5@1265.75,548.5 1265.75,524.51 1283.99,506.27
  Top Layer w8: 1283.99,506.27 1359.82,506.27 v1(1428.21,437.87) 2049.03,437.87 2581.71,970.55 2581.71,1606.26 2542.39,1645.59 J4.7@2455.59,1645.59 2228.89,1645.59 2188.73,1605.43 U2.19@1909.45,1605.43
  Bottom Layer w7: v1(1427.17,739.75) 1499.02,667.9 1499.02,508.68 v1(1428.21,437.87)
PA12: J6.3 U2.27 | length 674.3
  Top Layer w8: U2.27@1844.49,1729.45 1844.49,1833.69 2105.59,2094.8 J6.3@2105.59,2295.59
